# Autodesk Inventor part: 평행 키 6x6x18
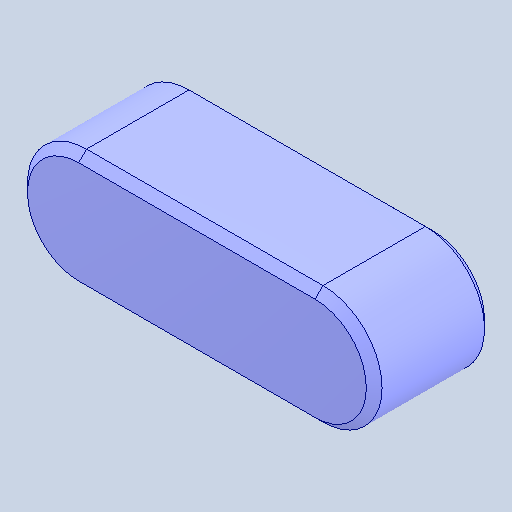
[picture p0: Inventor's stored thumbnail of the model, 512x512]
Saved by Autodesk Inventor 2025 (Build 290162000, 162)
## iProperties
Created: 2026-01
Part Number: 평행 키 6x6x18
Material: 강철, 연강
Description: 키 및 해당 키홈
Document SubType Name: Modeling
Designer: KDI
Density: 7.85 g/cm^3
Appearance: 기본값
Author: jhkim
Sending System: Autodesk Inventor 2026
Preprocessor: ST-DEVELOPER v20.1
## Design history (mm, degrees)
feature "Solid1"
node "솔리드1"
